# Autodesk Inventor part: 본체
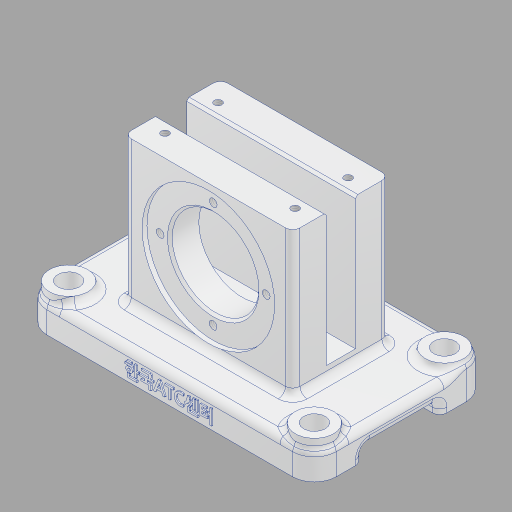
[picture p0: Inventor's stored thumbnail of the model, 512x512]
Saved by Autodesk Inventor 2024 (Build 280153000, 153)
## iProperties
Created: 2025-04
Part Number: 본체
Material: 알루미늄 6061
Document SubType Name: Modeling
Designer: kh_501
Density: 2.7 g/cm^3
Appearance: 알루미늄 - 평지
Mass: 493.091 g
Surface Area: 443.741 cm^2
Volume: 182.626 cm^3
Author: kh_501
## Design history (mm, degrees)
sketch "스케치1"
  geometry: L1 (60, -36)-(-60, -36); L2 (-60, -36)-(-60, 36); L3 (-60, 36)-(60, 36); L4 (60, 36)-(60, -36); L5 (60, -36)-(-60, 36); L6 (-60, -36)-(60, 36); 1 further point
  constraints: 12 end point, 2 midpoint, 2 parallel, 1 horizontal, 1 perpendicular
  dimensions: "d0" = 120 distance of L2.end L3.end; "d1" = 72 distance of L1.end L2.end
extrude "돌출1" new body sketch "스케치1" distance "d2" = 12; taper "d3" = 0 deg
sketch "스케치2"
  geometry: L1 (35, 20)-(-35, 20); L2 (-35, 20)-(-35, -20); L3 (-35, -20)-(35, -20); L4 (35, -20)-(35, 20); L5 (35, 20)-(-35, -20); L6 (-35, 20)-(35, -20); 1 further point
  constraints: 12 end point, 2 midpoint, 2 parallel, 1 horizontal, 1 perpendicular
  dimensions: "d4" = 40 distance between parallel lines of L3 L1; "d5" = 70 distance between parallel lines of L4 L2
extrude "돌출2" join sketch "스케치2" distance "d6" = 60; taper "d7" = 0 deg
sketch "스케치3"
  geometry: L1 (-35, 6)-(35, 6); L2 (35, 6)-(35, -6); L3 (35, -6)-(-35, -6); L4 (-35, -6)-(-35, 6); L5 (-35, 6)-(35, -6); L6 (35, 6)-(-35, -6); 1 further point
  constraints: 12 end point, 2 midpoint, 2 parallel, 1 horizontal, 1 perpendicular
  dimensions: "d8" = 70 distance of L2.end L3.end; "d9" = 12 distance of L1.end L2.end
extrude "돌출3" cut sketch "스케치3" distance "d10" = 55; taper "d11" = 0 deg
sketch "스케치4"
  geometry: L1 (60, 16)-(-60, 16); L2 (-60, 16)-(-60, -16); L3 (-60, -16)-(60, -16); L4 (60, -16)-(60, 16); L5 (60, 16)-(-60, -16); L6 (-60, 16)-(60, -16); 1 further point
  constraints: 12 end point, 2 midpoint, 2 parallel, 1 horizontal, 1 perpendicular
  dimensions: "d12" = 120 distance of L3.end L2.end; "d13" = 32 distance of L2.end L1.end
extrude "돌출4" cut sketch "스케치4" distance "d14" = 5; taper "d15" = 0 deg
sketch "스케치5"
  geometry: L1 (-25, -12)-(95, -12) reference; C1 r 17 at (35, 30); 3 further points
  constraints: 2 midpoint, 1 centre point, 1 vertical alignment
  dimensions: "d16" = 34 diameter of C1; "d17" = 42 distance of point (35, -12) C1.centre
extrude "돌출5" join sketch "스케치5" distance "d18" = 7; taper "d19" = 0 deg
sketch "스케치6"
  geometry: L1 (-51, 27)-(51, 27); L2 (51, 27)-(51, -27); L3 (51, -27)-(-51, -27); L4 (-51, -27)-(-51, 27); L5 (-51, 27)-(51, -27); L6 (51, 27)-(-51, -27); C1 r 8 at (-51, 27); C2 r 8 at (-51, -27); C3 r 8 at (51, -27); C4 r 8 at (51, 27); 5 further points
  constraints: 12 end point, 4 centre point, 4 coincident, 2 midpoint, 2 parallel, 1 horizontal, 1 perpendicular
  dimensions: "d20" = 102 distance of L2.end L3.end; "d21" = 54 distance of L1.end L2.end; "d22" = 16 diameter of C1; "d23" = 16 diameter of C2; "d24" = 16 diameter of C3; "d25" = 16 diameter of C4
extrude "돌출6" join sketch "스케치6" distance "d26" = 3; taper "d27" = 0 deg
sketch "스케치7"
  geometry: L1 (-102, 54)-(0, 54); L2 (0, 54)-(0, 0); L3 (0, 0)-(-102, 0); L4 (-102, 0)-(-102, 54); L5 (-102, 54)-(0, 0); L6 (0, 54)-(-102, 0); 5 further points
  constraints: 12 end point, 3 coincident, 2 midpoint, 2 parallel, 1 horizontal, 1 perpendicular, 1 point on line
  dimensions: "d28" = 54 distance between parallel lines of L3 L1; "d29" = 102 distance between parallel lines of L2 L4
hole "구멍1" sketch "스케치7" at (-102, 54), (-102, 0), (0, 0), (0, 54) diameter "d30" = 9; stored, may be unused: countersink angle "d34" = 90 deg, drill point angle "d36" = 118 deg; dims "d31" = 6, "d32" = 4, "d33" = 2, "d35" = 80.25
sketch "스케치8"
  geometry: C1 r 17 at (0, 0) reference; 2 further points
  constraints: 1 coincident
hole "구멍2" sketch "스케치8" at (0, 0) diameter "d37" = 22; stored, may be unused: countersink angle "d41" = 90 deg, drill point angle "d43" = 0 deg; dims "d38" = 6, "d39" = 4, "d40" = 2, "d42" = 8
sketch "스케치9"
  geometry: L1 (-25, -12)-(95, -12) reference; C1 r 27.5 at (35, 30); 2 further points
  constraints: 1 centre point, 1 midpoint, 1 vertical alignment
  dimensions: "d44" = 55 diameter of C1; "d45" = 42 distance of point (35, -12) C1.centre
extrude "돌출7" cut sketch "스케치9" distance "d46" = 2; taper "d47" = 0 deg
sketch "스케치10"
  geometry: C1 r 27.5 at (0, 0) reference; 2 further points
  constraints: 1 coincident
hole "구멍3" sketch "스케치10" at (0, 0) diameter "d48" = 36; stored, may be unused: countersink angle "d52" = 90 deg, drill point angle "d54" = 0 deg; dims "d49" = 6, "d50" = 4, "d51" = 2, "d53" = 17.75
sketch "스케치11" dims "d56" = 44
  geometry: L1 (-60, -42)-(60, -42) reference; 4 further points
  constraints: 3 vertical alignment, 1 midpoint, 2 other
  dimensions: "d57" = 42 distance of point (0, -42) point (0, 0)
hole "구멍4" sketch "스케치11" at (0, 22) diameter "d58" = 3.242; stored, may be unused: countersink angle "d62" = 90 deg, drill point angle "d64" = 120 deg; dims "d59" = 8, "d60" = 4, "d61" = 2, "d63" = 10
sketch "스케치12"
  geometry: L1 (-27, 11)-(27, 11); L2 (27, 11)-(27, -11); L3 (27, -11)-(-27, -11); L4 (-27, -11)-(-27, 11); L5 (-27, 11)-(27, -11); L6 (27, 11)-(-27, -11); 5 further points
  constraints: 12 end point, 4 coincident, 2 midpoint, 2 parallel, 1 horizontal, 1 perpendicular
  dimensions: "d68" = 54 distance of L2.end L3.end; "d69" = 22 distance of L1.end L2.end
hole "구멍5" sketch "스케치12" at (-27, 11), (-27, -11), (27, -11), (27, 11) diameter "d70" = 3.242; stored, may be unused: countersink angle "d74" = 90 deg, drill point angle "d76" = 120 deg; dims "d71" = 8, "d72" = 4, "d73" = 2, "d75" = 10
sketch "스케치13"
  geometry: L1 (0, 0)-(120, 0) reference; 4 further points
  constraints: 2 midpoint, 1 vertical alignment, 1 other
  dimensions: "d77" = 5 distance of point (60, 0) point (60, 5)
feature "엠보싱1" sketch "스케치13" dims "d0" = 120, "d1" = 72, "d8" = 70, "d9" = 12, "d78" = 0.5, "d79" = 0
fillet "모깎기1" dims "d80" = 9
fillet "모깎기2" dims "d81" = 3
fillet "모깎기3" dims "d82" = 3
fillet "모깎기4" dims "d83" = 3
sketch "스케치14"
  geometry: C1 r 15 at (35, -30); 1 further point
  constraints: 1 centre point, 1 vertical alignment
  dimensions: "d84" = 30 diameter of C1; "d85" = 42 distance of point (35, -72) C1.centre
extrude "돌출8" cut sketch "스케치14" distance "d86" = 5; taper "d87" = 0 deg
chamfer "모따기1" distance "d88" = 1; stored, may be unused: second distance "d89" = 2, angle "d90" = 45 deg
node "솔리드1"
pattern_circular "원형 패턴1" dims angle "d66" = 360 deg
feature "A9D066F2-1C7D-4E18-AEED-F7BC21143FA4" dims "d30" = 9, "d31" = 6, "d32" = 4, "d33" = 2, "d34" = 90 deg, "d35" = 80.25, "d36" = 118 deg
